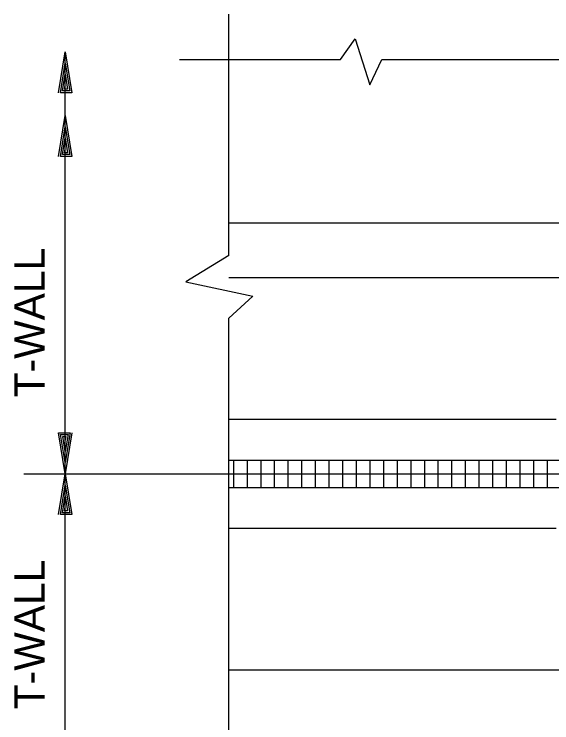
# Model space of a CAD drawing. Extents: x 44743.44 to 44747.1, y 44738.46 to 44741.29.
# Drawn here: x 44744.0233 to 44744.2286, y 44739.5722 to 44739.8431 of the extents above; entities that cross this region are included whole.
import ezdxf

# ---------------------------------------------------------------- set-up
doc = ezdxf.new("R2010")
doc.units = 0
for name, color, linetype in [('Level 1', 7, 'Continuous'), ('Level 10', 7, 'Continuous'), ('Level 2', 7, 'Continuous'), ('S-ANNO-TEXT', 7, 'Continuous')]:
    doc.layers.add(name, color=color, linetype=linetype)

msp = doc.modelspace()

# ---------------------------------------------------------------- linework, layer by layer
at = {"layer": 'Level 1'}
for p, q in [((44744.10524, 44739.75078), (44744.10524, 44739.84306)), ((44744.1479, 44739.82578), (44744.15348, 44739.83369)), ((44744.15348, 44739.83369), (44744.15907, 44739.81602)), ((44744.04274, 44739.66744), (44744.04274, 44739.82864)), ((44744.04274, 44739.82864), (44744.04274, 44739.82864)), ((44744.04274, 44739.82431), (44744.04274, 44739.82431)), ((44744.08634, 44739.82578), (44744.1479, 44739.82578)), ((44744.15907, 44739.81602), (44744.16371, 44739.82578)), ((44744.16371, 44739.82578), (44744.2818, 44739.82578)), ((44744.04274, 44739.79147), (44744.04274, 44739.79147)), ((44744.04166, 44739.78939), (44744.04166, 44739.78939)), ((44744.04249, 44739.79006), (44744.04249, 44739.79006)), ((44744.04366, 44739.79006), (44744.04366, 44739.79006)), ((44744.04449, 44739.78939), (44744.04449, 44739.78939)), ((44744.04016, 44739.78872), (44744.04016, 44739.78872)), ((44744.04091, 44739.78872), (44744.04091, 44739.78872)), ((44744.04533, 44739.78872), (44744.04533, 44739.78872)), ((44744.10524, 44739.55528), (44744.10524, 44739.72682)), ((44744.04274, 44739.67178), (44744.04274, 44739.67178)), ((44744.02699, 44739.66744), (44744.63277, 44739.66744)), ((44744.04274, 44739.50466), (44744.04274, 44739.66744)), ((44744.04274, 44739.66744), (44744.04274, 44739.66744)), ((44744.04274, 44739.66744), (44744.04274, 44739.66744)), ((44744.04274, 44739.66311), (44744.04274, 44739.66311))]:
    msp.add_line(p, q, dxfattribs=at)
for points in [[(44744.04016, 44739.81306), (44744.04274, 44739.82864), (44744.04533, 44739.81306), (44744.04091, 44739.81306), (44744.04274, 44739.82431), (44744.04449, 44739.81372), (44744.04166, 44739.81372), (44744.04274, 44739.82014), (44744.04366, 44739.81439), (44744.04249, 44739.81439), (44744.04274, 44739.81581)], [(44744.04016, 44739.78872), (44744.04274, 44739.80431), (44744.04533, 44739.78872), (44744.04091, 44739.78872), (44744.04274, 44739.79997), (44744.04449, 44739.78939), (44744.04166, 44739.78939), (44744.04274, 44739.79581), (44744.04366, 44739.79006), (44744.04249, 44739.79006), (44744.04274, 44739.79147)], [(44744.10524, 44739.75078), (44744.0888, 44739.74073), (44744.11438, 44739.73525), (44744.10524, 44739.72682)], [(44744.04533, 44739.68303), (44744.04274, 44739.66744), (44744.04016, 44739.68303), (44744.04458, 44739.68303), (44744.04274, 44739.67178), (44744.04099, 44739.68236), (44744.04383, 44739.68236), (44744.04274, 44739.67594), (44744.04183, 44739.68169), (44744.04299, 44739.68169), (44744.04274, 44739.68028)], [(44744.04016, 44739.65186), (44744.04274, 44739.66744), (44744.04533, 44739.65186), (44744.04091, 44739.65186), (44744.04274, 44739.66311), (44744.04449, 44739.65253), (44744.04166, 44739.65253), (44744.04274, 44739.65894), (44744.04366, 44739.65319), (44744.04249, 44739.65319), (44744.04274, 44739.65461)]]:
    msp.add_lwpolyline(points, dxfattribs=at)
at = {"layer": 'Level 10'}
for p, q in [((44744.10524, 44739.67265), (44744.34023, 44739.67265)), ((44744.10524, 44739.66223), (44744.33998, 44739.66223))]:
    msp.add_line(p, q, dxfattribs=at)
at = {"layer": 'Level 2'}
for p, q in [((44744.10524, 44739.76328), (44744.60524, 44739.76328)), ((44744.10524, 44739.74244), (44744.59, 44739.74244)), ((44744.10524, 44739.68828), (44744.23024, 44739.68828)), ((44744.10711, 44739.66223), (44744.10711, 44739.67265)), ((44744.11232, 44739.66223), (44744.11232, 44739.67265)), ((44744.11752, 44739.66223), (44744.11752, 44739.67265)), ((44744.12273, 44739.66223), (44744.12273, 44739.67265)), ((44744.12794, 44739.66223), (44744.12794, 44739.67265)), ((44744.13315, 44739.66223), (44744.13315, 44739.67265)), ((44744.13836, 44739.66223), (44744.13836, 44739.67265)), ((44744.14357, 44739.66223), (44744.14357, 44739.67265)), ((44744.14877, 44739.66223), (44744.14877, 44739.67265)), ((44744.15398, 44739.66223), (44744.15398, 44739.67265)), ((44744.15919, 44739.66223), (44744.15919, 44739.67265)), ((44744.1644, 44739.66223), (44744.1644, 44739.67265)), ((44744.16961, 44739.66223), (44744.16961, 44739.67265)), ((44744.17482, 44739.66223), (44744.17482, 44739.67265)), ((44744.18002, 44739.66223), (44744.18002, 44739.67265)), ((44744.18523, 44739.66223), (44744.18523, 44739.67265)), ((44744.19044, 44739.66223), (44744.19044, 44739.67265)), ((44744.19565, 44739.66223), (44744.19565, 44739.67265)), ((44744.20086, 44739.66223), (44744.20086, 44739.67265)), ((44744.20607, 44739.66223), (44744.20607, 44739.67265)), ((44744.21127, 44739.66223), (44744.21127, 44739.67265)), ((44744.21648, 44739.66223), (44744.21648, 44739.67265)), ((44744.22169, 44739.66223), (44744.22169, 44739.67265)), ((44744.2269, 44739.66223), (44744.2269, 44739.67265)), ((44744.10524, 44739.64661), (44744.23024, 44739.64661)), ((44744.10524, 44739.59244), (44744.60524, 44739.59244))]:
    msp.add_line(p, q, dxfattribs=at)

# ---------------------------------------------------------------- texts
at = {"layer": 'S-ANNO-TEXT'}
for p in [(44744.03493, 44739.6966), (44744.03493, 44739.57742)]:
    msp.add_text('T-WALL', height=0.011667, rotation=90, dxfattribs=at).set_placement(p)

doc.saveas('drawing.dxf')
